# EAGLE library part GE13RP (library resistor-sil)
SIL RESISTOR
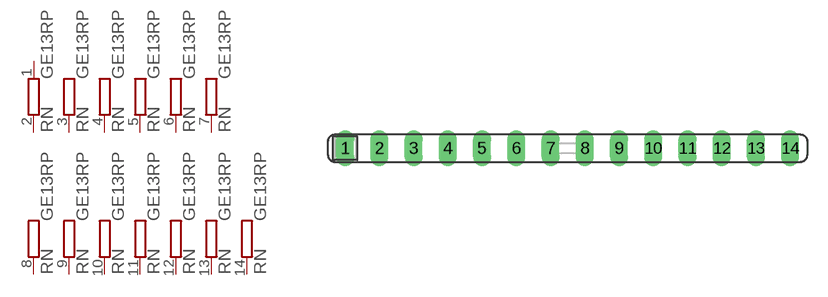
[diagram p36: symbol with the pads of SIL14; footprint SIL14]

Designator prefix RN; gates A=R-PV B=R-PV1 C=R-PV1 D=R-PV1 E=R-PV1 F=R-PV1 G=R-PV1 H=R-PV1 I=R-PV1 J=R-PV1 K=R-PV1 L=R-PV1 M=R-PV1

## GE13RP (OC_FARNELL: unknown; OC_NEWARK: unknown)  [SIL14]
1  A:1  pas
2  A:2  pas
3  B:2  pas
4  C:2  pas
5  D:2  pas
6  E:2  pas
7  F:2  pas
8  G:2  pas
9  H:2  pas
10  I:2  pas
11  J:2  pas
12  K:2  pas
13  L:2  pas
14  M:2  pas

## Footprint SIL14 (pad centres in mm)
Single In Line
drill 0.813 long: 1 -16.51,0; 2 -13.97,0; 3 -11.43,0; 4 -8.89,0; 5 -6.35,0; 6 -3.81,0; 7 -1.27,0; 8 1.27,0; 9 3.81,0; 10 6.35,0; 11 8.89,0; 12 11.43,0; 13 13.97,0; 14 16.51,0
